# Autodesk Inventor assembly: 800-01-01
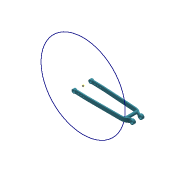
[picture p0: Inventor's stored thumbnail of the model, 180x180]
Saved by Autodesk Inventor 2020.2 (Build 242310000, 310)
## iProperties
Created: 2014-12
Part Number: 800-01-01
Document SubType Name: Assembly
Designer: F.Stasiak
Mass: 585.331 g
Surface Area: 715.479 cm^2
Volume: 216.789 cm^3
Density: 2.7 g/cm^3
Catalog Web Link: www.expertbooks.pl
Manager: www.cadconsulting.pl
Company: Fabian Stasiak CAD Consulting
Author: F.Stasiak
Subject: Zbiór ćwiczeń. Autodesk Inventor 2020. Kurs Professional
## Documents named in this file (3)
- C:\2020_Kurs_Professional\R3 Dynamika\Komponenty_dyn\800-01-01.iam
- C:\2020_Kurs_Professional\R3 Dynamika\Komponenty_dyn\800-02-Wahacz.ipt
- C:\2020_Kurs_Professional\R3 Dynamika\Komponenty_dyn\800-10-Koło.ipt
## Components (2 placed, 2 different names)
1. 800-02-Wahacz:1
2. 800-10-Koło:1
